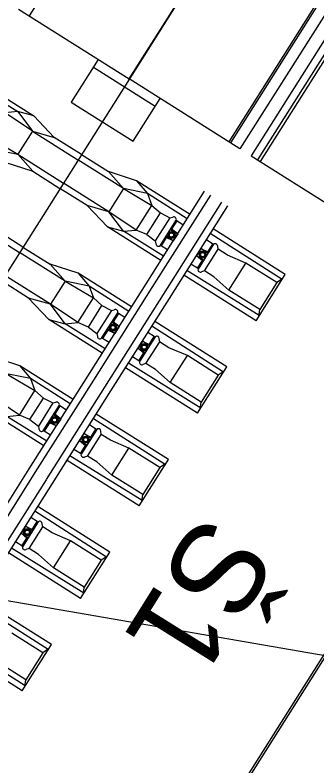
# Model space of a CAD drawing. Extents: x -743546 to -74, y -1128126 to -103.
# Drawn here: x -743176.668 to -743175.014, y -1127104.625 to -1127100.508 of the extents above; entities that cross this region are included whole.
import ezdxf

# ---------------------------------------------------------------- set-up
doc = ezdxf.new("R2010")
doc.units = 0
for name, color, linetype in [('_SVAH - Přesunutá', 7, 'Continuous'), ('KOL_ROST', 7, 'Continuous'), ('křížek', 7, 'Continuous'), ('OSA', 7, 'Continuous'), ('PREJEZD_KCE', 7, 'Continuous'), ('TRATIVOD', 7, 'Continuous'), ('Vrstva 53', 7, 'Continuous'), ('Vrstva 60', 7, 'Continuous')]:
    doc.layers.add(name, color=color, linetype=linetype)

# ---------------------------------------------------------------- blocks, each defined once
blk = doc.blocks.new('POINT_DISPLAY')
blk.add_line((0, 0), (0, 0))

msp = doc.modelspace()

# ---------------------------------------------------------------- linework, layer by layer
at = {"layer": '_SVAH - Přesunutá'}
msp.add_lwpolyline([(-743173.3378, -1127101.419), (-743176.5244, -1127106.4668)], dxfattribs=at)
at = {"layer": 'KOL_ROST'}
for p, q in [((-743176.0027, -1127100.7946), (-743176.0027, -1127100.7946)), ((-743176.8566, -1127100.8764), (-743176.564, -1127101.0611)), ((-743176.8721, -1127100.901), (-743176.6531, -1127101.0373)), ((-743176.6531, -1127101.0373), (-743176.7223, -1127101.0439)), ((-743176.5728, -1127101.1442), (-743176.7223, -1127101.0439)), ((-743176.564, -1127101.0611), (-743176.6531, -1127101.0373)), ((-743176.6531, -1127101.0373), (-743176.5728, -1127101.1442)), ((-743176.564, -1127101.0611), (-743176.4526, -1127101.1787)), ((-743176.5728, -1127101.1442), (-743176.6528, -1127101.2711)), ((-743176.5728, -1127101.1442), (-743176.4526, -1127101.1787)), ((-743176.5728, -1127101.1442), (-743176.323, -1127101.3019)), ((-743176.3043, -1127101.2723), (-743176.4526, -1127101.1787)), ((-743176.7839, -1127101.2445), (-743176.6528, -1127101.2711)), ((-743176.6528, -1127101.2711), (-743176.57, -1127101.3647)), ((-743176.0731, -1127101.4596), (-743176.323, -1127101.3019)), ((-743176.3043, -1127101.2723), (-743176.1559, -1127101.366)), ((-743176.7242, -1127101.3147), (-743176.57, -1127101.3647)), ((-743176.57, -1127101.3647), (-743176.4217, -1127101.4584)), ((-743176.0018, -1127101.416), (-743176.1559, -1127101.366)), ((-743176.0731, -1127101.4596), (-743176.1559, -1127101.366)), ((-743176.0018, -1127101.416), (-743175.9421, -1127101.4862)), ((-743175.7093, -1127101.6007), (-743176.0018, -1127101.416)), ((-743176.2734, -1127101.552), (-743176.4217, -1127101.4584)), ((-743176.0731, -1127101.4596), (-743176.1532, -1127101.5865)), ((-743176.0731, -1127101.4596), (-743175.9183, -1127101.5515)), ((-743175.9421, -1127101.4862), (-743176.0731, -1127101.4596)), ((-743175.9495, -1127101.9812), (-743175.6292, -1127101.4738)), ((-743175.9421, -1127101.4862), (-743175.9183, -1127101.5515)), ((-743175.7248, -1127101.6253), (-743175.9421, -1127101.4862)), ((-743175.9164, -1127102.002), (-743175.5961, -1127101.4947)), ((-743176.162, -1127101.6696), (-743176.2734, -1127101.552)), ((-743176.1532, -1127101.5865), (-743176.2734, -1127101.552)), ((-743176.0037, -1127101.6868), (-743175.9183, -1127101.5515)), ((-743175.9183, -1127101.5515), (-743175.8712, -1127101.593)), ((-743175.8555, -1127102.0404), (-743175.5352, -1127101.5331)), ((-743175.8224, -1127102.0613), (-743175.5022, -1127101.554)), ((-743176.0729, -1127101.6934), (-743176.1532, -1127101.5865)), ((-743175.9459, -1127101.7114), (-743175.8712, -1127101.593)), ((-743175.8712, -1127101.593), (-743175.8196, -1127101.62)), ((-743175.8196, -1127101.62), (-743175.8039, -1127101.6159)), ((-743175.7462, -1127101.6592), (-743175.7813, -1127101.6365)), ((-743176.893, -1127101.6516), (-743176.6432, -1127101.8093)), ((-743176.162, -1127101.6696), (-743176.0729, -1127101.6934)), ((-743175.8694, -1127101.8543), (-743176.162, -1127101.6696)), ((-743176.6246, -1127101.7797), (-743176.7729, -1127101.686)), ((-743176.0729, -1127101.6934), (-743176.0037, -1127101.6868)), ((-743175.8538, -1127101.8297), (-743176.0729, -1127101.6934)), ((-743175.9459, -1127101.7114), (-743175.8994, -1127101.7464)), ((-743175.8101, -1127101.6822), (-743175.8165, -1127101.683)), ((-743175.8165, -1127101.683), (-743175.777, -1127101.708)), ((-743175.777, -1127101.708), (-743175.8101, -1127101.6822)), ((-743175.777, -1127101.708), (-743175.801, -1127101.7459)), ((-743175.2053, -1127101.9577), (-743175.5983, -1127101.7062)), ((-743175.1875, -1127101.93), (-743175.5822, -1127101.6808)), ((-743175.8994, -1127101.7464), (-743175.8963, -1127101.7623)), ((-743175.8393, -1127101.7283), (-743175.8405, -1127101.721)), ((-743175.801, -1127101.7459), (-743175.8405, -1127101.721)), ((-743175.801, -1127101.7459), (-743175.8393, -1127101.7283)), ((-743175.585, -1127101.7632), (-743175.62, -1127101.7406)), ((-743176.6246, -1127101.7797), (-743176.4762, -1127101.8733)), ((-743175.8325, -1127101.7958), (-743175.868, -1127101.7739)), ((-743175.65, -1127101.7881), (-743175.6739, -1127101.8261)), ((-743175.6105, -1127101.813), (-743175.65, -1127101.7881)), ((-743175.65, -1127101.7881), (-743175.6125, -1127101.8069)), ((-743175.5553, -1127101.792), (-743175.5575, -1127101.7746)), ((-743175.5553, -1127101.792), (-743175.5575, -1127101.7746)), ((-743175.5042, -1127101.8247), (-743175.5554, -1127101.7921)), ((-743175.5042, -1127101.8247), (-743175.5554, -1127101.7921)), ((-743176.3934, -1127101.967), (-743176.6432, -1127101.8093)), ((-743175.6739, -1127101.8261), (-743175.6344, -1127101.851)), ((-743175.6739, -1127101.8261), (-743175.6416, -1127101.8531)), ((-743175.6125, -1127101.8069), (-743175.6105, -1127101.813)), ((-743175.4035, -1127101.8676), (-743175.5042, -1127101.8247)), ((-743175.4035, -1127101.8676), (-743175.5042, -1127101.8247)), ((-743176.3221, -1127101.9233), (-743176.4762, -1127101.8733)), ((-743176.3934, -1127101.967), (-743176.4762, -1127101.8733)), ((-743175.6691, -1127101.8965), (-743175.7046, -1127101.8746)), ((-743175.6416, -1127101.8531), (-743175.6344, -1127101.851)), ((-743175.4969, -1127102.0156), (-743175.4035, -1127101.8676)), ((-743175.2344, -1127101.9743), (-743175.4035, -1127101.8676)), ((-743176.3221, -1127101.9233), (-743176.2624, -1127101.9935)), ((-743176.0296, -1127102.108), (-743176.3221, -1127101.9233)), ((-743175.3302, -1127102.1555), (-743175.7263, -1127101.909)), ((-743175.6304, -1127101.9109), (-743175.647, -1127101.9165)), ((-743175.5789, -1127101.9431), (-743175.6304, -1127101.9109)), ((-743176.5937, -1127102.0594), (-743176.742, -1127101.9657)), ((-743176.3934, -1127101.967), (-743176.4735, -1127102.0938)), ((-743176.3934, -1127101.967), (-743176.2386, -1127102.0588)), ((-743176.2624, -1127101.9935), (-743176.3934, -1127101.967)), ((-743175.3477, -1127102.1837), (-743175.7424, -1127101.9345)), ((-743175.4969, -1127102.0156), (-743175.5789, -1127101.9431)), ((-743175.3477, -1127102.1837), (-743175.1875, -1127101.93)), ((-743175.2025, -1127101.9537), (-743175.2344, -1127101.9743)), ((-743176.2698, -1127102.4885), (-743175.9495, -1127101.9812)), ((-743176.2624, -1127101.9935), (-743176.2386, -1127102.0588)), ((-743176.0451, -1127102.1326), (-743176.2624, -1127101.9935)), ((-743176.2367, -1127102.5094), (-743175.9164, -1127102.002)), ((-743175.2344, -1127101.9743), (-743175.3278, -1127102.1223)), ((-743176.1758, -1127102.5478), (-743175.8555, -1127102.0405)), ((-743175.3278, -1127102.1223), (-743175.4969, -1127102.0156)), ((-743176.4823, -1127102.177), (-743176.5937, -1127102.0594)), ((-743176.4735, -1127102.0938), (-743176.5937, -1127102.0594)), ((-743176.324, -1127102.1941), (-743176.2386, -1127102.0588)), ((-743176.2386, -1127102.0588), (-743176.1915, -1127102.1004)), ((-743176.1427, -1127102.5687), (-743175.8225, -1127102.0613)), ((-743176.3932, -1127102.2007), (-743176.4735, -1127102.0938)), ((-743176.2662, -1127102.2188), (-743176.1915, -1127102.1004)), ((-743176.1915, -1127102.1004), (-743176.1399, -1127102.1274)), ((-743176.1399, -1127102.1274), (-743176.1242, -1127102.1233)), ((-743175.3327, -1127102.16), (-743175.3278, -1127102.1223)), ((-743176.0665, -1127102.1665), (-743176.1016, -1127102.1439)), ((-743176.4823, -1127102.177), (-743176.3932, -1127102.2007)), ((-743176.1897, -1127102.3617), (-743176.4823, -1127102.177)), ((-743176.3932, -1127102.2007), (-743176.324, -1127102.1941)), ((-743176.1741, -1127102.337), (-743176.3932, -1127102.2007)), ((-743176.1304, -1127102.1896), (-743176.1368, -1127102.1904)), ((-743176.1368, -1127102.1904), (-743176.0973, -1127102.2153)), ((-743176.0973, -1127102.2153), (-743176.1304, -1127102.1896)), ((-743175.5256, -1127102.465), (-743175.9186, -1127102.2136)), ((-743175.5078, -1127102.4374), (-743175.9025, -1127102.1882)), ((-743176.2662, -1127102.2188), (-743176.2197, -1127102.2537)), ((-743176.2197, -1127102.2537), (-743176.2166, -1127102.2697)), ((-743176.1596, -1127102.2357), (-743176.1608, -1127102.2284)), ((-743176.1213, -1127102.2533), (-743176.1608, -1127102.2284)), ((-743176.1213, -1127102.2533), (-743176.1596, -1127102.2357)), ((-743176.0973, -1127102.2153), (-743176.1213, -1127102.2533)), ((-743175.9053, -1127102.2706), (-743175.9403, -1127102.248)), ((-743176.1527, -1127102.3031), (-743176.1883, -1127102.2812)), ((-743175.9702, -1127102.2955), (-743175.9942, -1127102.3334)), ((-743175.9308, -1127102.3204), (-743175.9702, -1127102.2955)), ((-743175.9702, -1127102.2955), (-743175.9327, -1127102.3143)), ((-743175.8756, -1127102.2994), (-743175.8778, -1127102.2819)), ((-743175.8756, -1127102.2994), (-743175.8778, -1127102.2819)), ((-743175.9942, -1127102.3334), (-743175.9547, -1127102.3584)), ((-743175.9942, -1127102.3334), (-743175.9619, -1127102.3604)), ((-743175.9327, -1127102.3143), (-743175.9308, -1127102.3204)), ((-743175.8245, -1127102.3321), (-743175.8757, -1127102.2995)), ((-743175.8245, -1127102.3321), (-743175.8757, -1127102.2995)), ((-743175.7238, -1127102.3749), (-743175.8245, -1127102.3321)), ((-743175.7238, -1127102.3749), (-743175.8245, -1127102.3321)), ((-743175.9619, -1127102.3604), (-743175.9547, -1127102.3584)), ((-743175.8172, -1127102.5229), (-743175.7238, -1127102.3749)), ((-743175.5547, -1127102.4817), (-743175.7238, -1127102.3749)), ((-743176.6424, -1127102.4307), (-743176.7965, -1127102.3807)), ((-743175.6505, -1127102.6629), (-743176.0466, -1127102.4164)), ((-743175.9894, -1127102.4038), (-743176.0249, -1127102.382)), ((-743175.9506, -1127102.4183), (-743175.9673, -1127102.4238)), ((-743175.8992, -1127102.4505), (-743175.9506, -1127102.4183)), ((-743176.6424, -1127102.4307), (-743176.5827, -1127102.5009)), ((-743176.3498, -1127102.6154), (-743176.6424, -1127102.4307)), ((-743175.6679, -1127102.6911), (-743176.0627, -1127102.4419)), ((-743175.8172, -1127102.5229), (-743175.8992, -1127102.4505)), ((-743175.6679, -1127102.6911), (-743175.5078, -1127102.4374)), ((-743175.5227, -1127102.4611), (-743175.5547, -1127102.4817)), ((-743176.7137, -1127102.4743), (-743176.5588, -1127102.5662)), ((-743176.5827, -1127102.5009), (-743176.7137, -1127102.4743)), ((-743176.59, -1127102.9959), (-743176.2698, -1127102.4885)), ((-743176.5827, -1127102.5009), (-743176.5588, -1127102.5662)), ((-743176.3654, -1127102.64), (-743176.5827, -1127102.5009)), ((-743175.5547, -1127102.4817), (-743175.6481, -1127102.6297)), ((-743176.557, -1127103.0167), (-743176.2367, -1127102.5094)), ((-743175.6481, -1127102.6297), (-743175.8172, -1127102.5229)), ((-743176.6442, -1127102.7015), (-743176.5588, -1127102.5662)), ((-743176.5588, -1127102.5662), (-743176.5117, -1127102.6077)), ((-743176.4961, -1127103.0551), (-743176.1758, -1127102.5478)), ((-743176.463, -1127103.076), (-743176.1427, -1127102.5687)), ((-743176.5865, -1127102.7261), (-743176.5117, -1127102.6077)), ((-743176.5117, -1127102.6077), (-743176.4602, -1127102.6347)), ((-743176.4602, -1127102.6347), (-743176.4445, -1127102.6306)), ((-743176.3868, -1127102.6739), (-743176.4219, -1127102.6512)), ((-743175.653, -1127102.6674), (-743175.6481, -1127102.6297)), ((-743176.51, -1127102.869), (-743176.8025, -1127102.6843)), ((-743176.7134, -1127102.7081), (-743176.6442, -1127102.7015)), ((-743176.4944, -1127102.8444), (-743176.7134, -1127102.7081)), ((-743176.4507, -1127102.6969), (-743176.4571, -1127102.6977)), ((-743176.4571, -1127102.6977), (-743176.4176, -1127102.7227)), ((-743176.4176, -1127102.7227), (-743176.4507, -1127102.6969)), ((-743175.8281, -1127102.9447), (-743176.2228, -1127102.6955)), ((-743176.5865, -1127102.7261), (-743176.5399, -1127102.7611)), ((-743176.4798, -1127102.743), (-743176.481, -1127102.7357)), ((-743176.4416, -1127102.7606), (-743176.481, -1127102.7357)), ((-743176.4416, -1127102.7606), (-743176.4798, -1127102.743)), ((-743176.4176, -1127102.7227), (-743176.4416, -1127102.7606)), ((-743175.8459, -1127102.9724), (-743176.2388, -1127102.7209)), ((-743176.5399, -1127102.7611), (-743176.5369, -1127102.777)), ((-743176.473, -1127102.8105), (-743176.5086, -1127102.7886)), ((-743176.2256, -1127102.7779), (-743176.2606, -1127102.7553)), ((-743176.1959, -1127102.8067), (-743176.198, -1127102.7893)), ((-743176.1959, -1127102.8067), (-743176.198, -1127102.7893)), ((-743176.2905, -1127102.8028), (-743176.3145, -1127102.8408)), ((-743176.251, -1127102.8277), (-743176.2905, -1127102.8028)), ((-743176.2905, -1127102.8028), (-743176.253, -1127102.8216)), ((-743176.253, -1127102.8216), (-743176.251, -1127102.8277)), ((-743176.1448, -1127102.8394), (-743176.1959, -1127102.8068)), ((-743176.1448, -1127102.8394), (-743176.1959, -1127102.8068)), ((-743176.3145, -1127102.8408), (-743176.275, -1127102.8657)), ((-743176.3145, -1127102.8408), (-743176.2821, -1127102.8678)), ((-743176.2821, -1127102.8678), (-743176.275, -1127102.8657)), ((-743176.0441, -1127102.8823), (-743176.1448, -1127102.8394)), ((-743176.0441, -1127102.8823), (-743176.1448, -1127102.8394)), ((-743176.3097, -1127102.9112), (-743176.3452, -1127102.8893)), ((-743176.1375, -1127103.0303), (-743176.0441, -1127102.8823)), ((-743175.875, -1127102.989), (-743176.0441, -1127102.8823)), ((-743175.9882, -1127103.1984), (-743176.383, -1127102.9492)), ((-743175.9708, -1127103.1702), (-743176.3669, -1127102.9237)), ((-743176.2709, -1127102.9256), (-743176.2876, -1127102.9312)), ((-743176.2195, -1127102.9578), (-743176.2709, -1127102.9256)), ((-743175.9882, -1127103.1984), (-743175.8281, -1127102.9447)), ((-743176.9103, -1127103.5032), (-743176.59, -1127102.9959)), ((-743176.1375, -1127103.0303), (-743176.2195, -1127102.9578)), ((-743175.875, -1127102.989), (-743175.9684, -1127103.137)), ((-743175.843, -1127102.9684), (-743175.875, -1127102.989)), ((-743176.8773, -1127103.5241), (-743176.557, -1127103.0167)), ((-743175.9684, -1127103.137), (-743176.1375, -1127103.0303)), ((-743176.8164, -1127103.5625), (-743176.4961, -1127103.0552)), ((-743176.7833, -1127103.5834), (-743176.463, -1127103.076)), ((-743175.9733, -1127103.1747), (-743175.9684, -1127103.137)), ((-743176.1662, -1127103.4797), (-743176.5591, -1127103.2283)), ((-743176.1484, -1127103.4521), (-743176.5431, -1127103.2029)), ((-743176.5459, -1127103.2853), (-743176.5809, -1127103.2627)), ((-743176.6108, -1127103.3102), (-743176.6348, -1127103.3481)), ((-743176.5713, -1127103.3351), (-743176.6108, -1127103.3102)), ((-743176.6108, -1127103.3102), (-743176.5733, -1127103.329)), ((-743176.5162, -1127103.3141), (-743176.5183, -1127103.2966)), ((-743176.5162, -1127103.3141), (-743176.5183, -1127103.2966)), ((-743176.465, -1127103.3468), (-743176.5162, -1127103.3142)), ((-743176.465, -1127103.3468), (-743176.5162, -1127103.3142)), ((-743176.6348, -1127103.3481), (-743176.5953, -1127103.3731)), ((-743176.6348, -1127103.3481), (-743176.6024, -1127103.3751)), ((-743176.5733, -1127103.329), (-743176.5713, -1127103.3351)), ((-743176.3644, -1127103.3896), (-743176.465, -1127103.3468)), ((-743176.3644, -1127103.3896), (-743176.465, -1127103.3468)), ((-743176.63, -1127103.4185), (-743176.6654, -1127103.3967)), ((-743176.6024, -1127103.3751), (-743176.5953, -1127103.3731)), ((-743176.4578, -1127103.5376), (-743176.3644, -1127103.3896)), ((-743176.1953, -1127103.4964), (-743176.3644, -1127103.3896)), ((-743176.2911, -1127103.6776), (-743176.6872, -1127103.4311)), ((-743176.5912, -1127103.433), (-743176.6079, -1127103.4385)), ((-743176.5398, -1127103.4652), (-743176.5912, -1127103.433)), ((-743176.3085, -1127103.7058), (-743176.7032, -1127103.4566)), ((-743176.4578, -1127103.5376), (-743176.5398, -1127103.4652)), ((-743176.3085, -1127103.7058), (-743176.1484, -1127103.4521)), ((-743176.1633, -1127103.4758), (-743176.1953, -1127103.4964)), ((-743176.1953, -1127103.4964), (-743176.2887, -1127103.6444)), ((-743176.2887, -1127103.6444), (-743176.4578, -1127103.5376)), ((-743176.2936, -1127103.6821), (-743176.2887, -1127103.6444)), ((-743176.4865, -1127103.9871), (-743176.8794, -1127103.7356)), ((-743176.4686, -1127103.9594), (-743176.8634, -1127103.7102)), ((-743176.5155, -1127104.0037), (-743176.6847, -1127103.897)), ((-743176.6114, -1127104.1849), (-743177.0074, -1127103.9384)), ((-743176.6288, -1127104.2131), (-743177.0235, -1127103.9639)), ((-743176.6288, -1127104.2131), (-743176.4686, -1127103.9594)), ((-743176.4836, -1127103.9831), (-743176.5155, -1127104.0037)), ((-743176.5155, -1127104.0037), (-743176.609, -1127104.1517)), ((-743176.609, -1127104.1517), (-743176.7781, -1127104.045)), ((-743176.6138, -1127104.1894), (-743176.609, -1127104.1517))]:
    msp.add_line(p, q, dxfattribs=at)
for points in [[(-743176.8548, -1127101.1377), (-743176.8077, -1127101.1792), (-743176.6528, -1127101.2711), (-743176.403, -1127101.4288)], [(-743175.9459, -1127101.7114), (-743176.0037, -1127101.6868), (-743176.1532, -1127101.5865), (-743176.403, -1127101.4288)], [(-743175.8196, -1127101.62), (-743175.8994, -1127101.7464)], [(-743175.8731, -1127101.7727), (-743175.7846, -1127101.6325)], [(-743175.7813, -1127101.6365), (-743175.8101, -1127101.6822)], [(-743175.7813, -1127101.6365), (-743175.7846, -1127101.6325)], [(-743175.8393, -1127101.7283), (-743175.868, -1127101.7739)], [(-743175.868, -1127101.7739), (-743175.8731, -1127101.7727)], [(-743175.58, -1127101.7647), (-743175.6656, -1127101.9004)], [(-743175.6304, -1127101.9109), (-743175.5553, -1127101.792)], [(-743175.6126, -1127101.8069), (-743175.585, -1127101.7632)], [(-743175.585, -1127101.7632), (-743175.58, -1127101.7647)], [(-743175.585, -1127101.7632), (-743175.58, -1127101.7647)], [(-743175.6691, -1127101.8965), (-743175.6417, -1127101.853)], [(-743175.6691, -1127101.8965), (-743175.6656, -1127101.9004)], [(-743176.2662, -1127102.2188), (-743176.324, -1127102.1941), (-743176.4735, -1127102.0938), (-743176.7233, -1127101.9361)], [(-743176.1399, -1127102.1274), (-743176.2197, -1127102.2537)], [(-743176.1934, -1127102.28), (-743176.1049, -1127102.1398)], [(-743176.1016, -1127102.1439), (-743176.1304, -1127102.1896)], [(-743176.1016, -1127102.1439), (-743176.1049, -1127102.1398)], [(-743176.1596, -1127102.2357), (-743176.1883, -1127102.2812)], [(-743176.1883, -1127102.2812), (-743176.1934, -1127102.28)], [(-743175.9002, -1127102.272), (-743175.9859, -1127102.4078)], [(-743175.9329, -1127102.3142), (-743175.9053, -1127102.2706)], [(-743175.9053, -1127102.2706), (-743175.9002, -1127102.272)], [(-743175.9053, -1127102.2706), (-743175.9002, -1127102.272)], [(-743175.9506, -1127102.4183), (-743175.8756, -1127102.2994)], [(-743175.9894, -1127102.4038), (-743175.962, -1127102.3603)], [(-743175.9894, -1127102.4038), (-743175.9859, -1127102.4078)], [(-743176.5865, -1127102.7261), (-743176.6442, -1127102.7015), (-743176.7938, -1127102.6012), (-743177.0436, -1127102.4435)], [(-743176.4602, -1127102.6347), (-743176.5399, -1127102.7611)], [(-743176.5137, -1127102.7874), (-743176.4251, -1127102.6472)], [(-743176.4219, -1127102.6512), (-743176.4507, -1127102.6969)], [(-743176.4219, -1127102.6512), (-743176.4251, -1127102.6472)], [(-743176.4798, -1127102.743), (-743176.5086, -1127102.7886)], [(-743176.5086, -1127102.7886), (-743176.5137, -1127102.7874)], [(-743176.2205, -1127102.7794), (-743176.3062, -1127102.9151)], [(-743176.2531, -1127102.8216), (-743176.2256, -1127102.7779)], [(-743176.2256, -1127102.7779), (-743176.2205, -1127102.7794)], [(-743176.2256, -1127102.7779), (-743176.2205, -1127102.7794)], [(-743176.2709, -1127102.9256), (-743176.1959, -1127102.8067)], [(-743176.3097, -1127102.9112), (-743176.2822, -1127102.8677)], [(-743176.3097, -1127102.9112), (-743176.3062, -1127102.9151)], [(-743176.5408, -1127103.2867), (-743176.6265, -1127103.4225)], [(-743176.5912, -1127103.433), (-743176.5162, -1127103.3141)], [(-743176.5734, -1127103.3289), (-743176.5459, -1127103.2853)], [(-743176.5459, -1127103.2853), (-743176.5408, -1127103.2867)], [(-743176.5459, -1127103.2853), (-743176.5408, -1127103.2867)], [(-743176.63, -1127103.4185), (-743176.6025, -1127103.375)], [(-743176.63, -1127103.4185), (-743176.6265, -1127103.4225)]]:
    msp.add_lwpolyline(points, dxfattribs=at)
for centre, radius in [((-743175.8109, -1127101.7136), 0.0195), ((-743175.8109, -1127101.7136), 0.0155), ((-743175.8109, -1127101.7136), 0.0115), ((-743175.6402, -1127101.8213), 0.0195), ((-743175.6402, -1127101.8213), 0.0155), ((-743175.6402, -1127101.8213), 0.0115), ((-743176.1312, -1127102.2209), 0.0195), ((-743176.1312, -1127102.2209), 0.0155), ((-743176.1312, -1127102.2209), 0.0115), ((-743175.9604, -1127102.3286), 0.0195), ((-743175.9604, -1127102.3286), 0.0155), ((-743175.9604, -1127102.3286), 0.0115), ((-743176.4515, -1127102.7283), 0.0195), ((-743176.4515, -1127102.7283), 0.0155), ((-743176.4515, -1127102.7283), 0.0115), ((-743176.2807, -1127102.836), 0.0195), ((-743176.2807, -1127102.836), 0.0155), ((-743176.2807, -1127102.836), 0.0115), ((-743176.601, -1127103.3433), 0.0195), ((-743176.601, -1127103.3433), 0.0155), ((-743176.601, -1127103.3433), 0.0115)]:
    msp.add_circle(centre, radius, dxfattribs=at)
for centre, radius, start, end in [((-743175.7985, -1127101.6292), 0.0143, 346.7248, 112.2532), ((-743175.5711, -1127101.7751), 0.0137, 2.1748, 130.3968), ((-743175.5711, -1127101.7751), 0.0137, 2.1748, 130.3968), ((-743175.882, -1127101.7615), 0.0143, 183.2195, 308.7478), ((-743175.6524, -1127101.9039), 0.0137, 165.0758, 293.2978), ((-743176.1188, -1127102.1365), 0.0143, 346.7248, 112.2532), ((-743176.2023, -1127102.2688), 0.0143, 183.2195, 308.7478), ((-743175.8914, -1127102.2824), 0.0137, 2.1748, 130.3968), ((-743175.8914, -1127102.2824), 0.0137, 2.1748, 130.3968), ((-743175.9727, -1127102.4113), 0.0137, 165.0758, 293.2978), ((-743176.4391, -1127102.6439), 0.0143, 346.7248, 112.2532), ((-743176.5226, -1127102.7762), 0.0143, 183.2195, 308.7478), ((-743176.2117, -1127102.7898), 0.0137, 2.1748, 130.3968), ((-743176.2117, -1127102.7898), 0.0137, 2.1748, 130.3968), ((-743176.293, -1127102.9186), 0.0137, 165.0758, 293.2978), ((-743176.532, -1127103.2971), 0.0137, 2.1748, 130.3968), ((-743176.532, -1127103.2971), 0.0137, 2.1748, 130.3968), ((-743176.6133, -1127103.426), 0.0137, 165.0758, 293.2978)]:
    msp.add_arc(centre, radius, start, end, dxfattribs=at)
at = {"layer": 'OSA'}
msp.add_lwpolyline([(-743169.5301, -1127090.5416), (-743178.7118, -1127105.0859)], dxfattribs=at)
at = {"layer": 'PREJEZD_KCE'}
for p, q in [((-743175.6297, -1127098.9899), (-743176.5906, -1127100.512)), ((-743175.0818, -1127099.3359), (-743176.0427, -1127100.8579)), ((-743176.0427, -1127100.8579), (-743175.0818, -1127099.3359)), ((-743175.4947, -1127101.2038), (-743174.5338, -1127099.6818)), ((-743175.4867, -1127101.2089), (-743174.5258, -1127099.6868)), ((-743174.4751, -1127099.7189), (-743175.4359, -1127101.2409)), ((-743174.4142, -1127099.7573), (-743175.3751, -1127101.2794)), ((-743174.3782, -1127099.78), (-743175.3391, -1127101.3021)), ((-743174.3643, -1127099.7888), (-743175.3252, -1127101.3108)), ((-743176.6494, -1127100.4749), (-743176.0427, -1127100.8579)), ((-743176.2118, -1127100.7512), (-743176.3597, -1127100.9854)), ((-743176.2385, -1127100.7935), (-743175.9002, -1127101.007)), ((-743175.4359, -1127101.2409), (-743176.0427, -1127100.8579)), ((-743176.0214, -1127101.1989), (-743175.8735, -1127100.9647)), ((-743176.3597, -1127100.9854), (-743176.0214, -1127101.1989)), ((-743175.3751, -1127101.2794), (-743174.7781, -1127101.6562))]:
    msp.add_line(p, q, dxfattribs=at)
at = {"layer": 'TRATIVOD'}
msp.add_lwpolyline([(-743175.6368, -1127105.0856), (-743168.3992, -1127093.6207), (-743157.3842, -1127076.1722), (-743151.7749, -1127072.3106)], dxfattribs=at)
at = {"layer": 'Vrstva 53'}
msp.add_lwpolyline([(-743183.34, -1127102.57), (-743171.62, -1127104.6), (-743183.01, -1127122.02), (-743195.51, -1127141.13), (-743203.92, -1127154.43), (-743215.95, -1127172.74), (-743210.36, -1127174.02), (-743237.28, -1127205.49), (-743245.75, -1127220.06), (-743259.48, -1127245.93)], dxfattribs=at)
at = {"layer": 'Vrstva 60'}
msp.add_line((-743176.043, -1127100.858), (-743176.043, -1127100.858), dxfattribs=at)

# ---------------------------------------------------------------- block references
at = {"layer": 'křížek', "xscale": 10, "yscale": 10, "rotation": 61.14491455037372}
msp.add_blockref('POINT_DISPLAY', (-743176.0427, -1127100.8579), dxfattribs=at)

# ---------------------------------------------------------------- texts
at = {"layer": 'TRATIVOD'}
msp.add_text('Š1', height=0.5, rotation=238, dxfattribs=at).set_placement((-743175.6459, -1127103.2231))

doc.saveas('drawing.dxf')
